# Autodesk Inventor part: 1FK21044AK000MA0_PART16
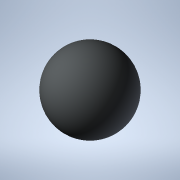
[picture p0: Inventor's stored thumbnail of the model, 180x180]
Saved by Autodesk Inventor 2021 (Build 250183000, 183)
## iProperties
Created: 2025-04
Part Number: 1FK21044AK000MA0_PART16
Material: Generic
Catalog Web Link: www.3dfindit.com
Description: -Servo synchronous motor
Document SubType Name: Modeling
Designer: psAdmin
Mass: 0.137258 g
Surface Area: 1.2868 cm^2
Volume: 0.137258 cm^3
Density: 1 g/cm^3
Appearance: PSOLRGB-212-217-219
Category: PARTsolutions
Title: 1FK21044AK000MA0_PART16
Author: Cadenas PARTsolutions
Comments: Servo synchronous motor
Sending System: PARTsolutions
Preprocessor: ST-DEVELOPER v19.3
PSOL_IDENT_0: {$CADENAS_DATA/23d-libs/siemens_ag/_cat_/87/f4/1fk21044ak000ma0.prj},216 {VTYP=3D},{NB=1FK21044AK000
PSOL_IDENT_1: MA0_PART16},{LINA=1FK21044AK000MA0_PART16},{NN=1FK21044AK000MA0_PART16},{NOPRJ=TRUE},{DATE=19.08.202
PSOL_IDENT_2: 5 14:00:48},{GEOMDATE=30.07.2025 02:00:50},{VERSION=},{LINEID=10},{WBVAR=},{WBNUMERIC=}  {NB=1FK2104
PSOL_IDENT_3: 4AK000MA0_PART16},{LINA=1FK21044AK000MA0_PART16},{KT=DUMMY},{PREVIEW=../../../_pool_/cb/72/p_d211_xx
PSOL_IDENT_4: _00434j.png},{DESCSHORT=SIMOTICS S-1FK2 HD, SINAMICS S210 3AC 400V-480V, 0.95 Nm, 6000 rpm},{DESCLON
PSOL_IDENT_5: G=SIMOTICS S-1FK2 HD servo motor M0=1.27 Nm; PN = 0.6 kW at nN=6000 rpm (380-480 V); PN = 0.4 kW at
PSOL_IDENT_6: nN=3000 rpm (200-240 V); degree of protection IP64; cylindrical shaft D19x40mm; absolute encoder 22-
PSOL_IDENT_7: bit + 12-bit multiturn (encoder AM22DQC); with OCC interface; plug size M17, rotatable; SIMOTICS S-1
PSOL_IDENT_8: FK2 servomotorfor a wide range of uses in industrial environments. SIMOTICS S‑1FK2 servomotors are c
PSOL_IDENT_9: ompact synchronous motors with a high dynamic performance that set themselves apart as a result of t
PSOL_IDENT_10: heir high power density, degree of protection and overload capability. The motors are available in t
PSOL_IDENT_11: wo variants: as High Dynamic variant (highest dynamic performance as a result of the low intrinsic m
PSOL_IDENT_12: oment of inertia for applications demanding a high dynamic performance with low moved masses) - and
PSOL_IDENT_13: as Compact variant (precise and stable closed-loop control for medium up to large moved masses as a
PSOL_IDENT_14: result of a medium intrinsic moment of inertia). SIMOTICSS‑1FK2 servomotors fully exploit their stre
PSOL_IDENT_15: ngths in a system with the SINAMICSS210 frequency converter and simple connection using the one cabl
PSOL_IDENT_16: e connection (OCC). Advantages include the short control and positioning times, fast and precise cor
PSOL_IDENT_17: rection of disturbing quantities as well as stable control with a high dynamic performance. The serv
PSOL_IDENT_18: o motors can be configured to address a wide range of requirements. For example with and without hol
PSOL_IDENT_19: ding brake, IP64 or IP65 degree of protection, singleturn or multiturn absolute encoders - to name j
PSOL_IDENT_20: ust a few. Further, the servomotors are available in different shaft heights extending from 20 to 10
PSOL_IDENT_21: 0. A shaft sealing ring is available to achieve an IP65 degree of protection and for subsequent moun
PSOL_IDENT_22: ting at the motor or as spare part. SIMOTICS - the optimum motor for each and every motion control a
PSOL_IDENT_23: pplication.},{INTNO=195125056312},{SUPPLIERALTNO=1FK2104-4AK00-0MA0},{MANUID=1FK21044AK000MA0},{MANU
PSOL_IDENT_24: NAME=Siemens},{MANUTYPEDESC=Synchronous motor 1FK2-HD 1,27 Nm},{AAU732=SIMOTICS},{AAO057=S-1FK2},{AA
PSOL_IDENT_25: U734=SIMOTICS S-1FK2 HD servo motor M0=1.27 Nm; PN = 0.6 kW at nN=6000 rpm (380-480 V); PN = 0.4 kW
PSOL_IDENT_26: at nN=3000 rpm (200-240 V); degree of protection IP64; cylindrical shaft D19x40mm; absolute encoder
PSOL_IDENT_27: 22-bit + 12-bit multiturn (encoder AM22DQC); with OCC interface; plug size M17, rotatable;},{AAW338=
PSOL_IDENT_28: Synchronous motor 1FK2-HD 1,27 Nm},{AAO742=SIMOTICS},{AAO663=4042948690994},{NOCUPEROU=1},{PRICEQUAN
PSOL_IDENT_29: TITY=1},{QUANTITYMIN=1},{QUANTITYINT=1},{CTN=85015100},{COO=DE},{AAO676=1FK2104-4AK00-0MA0},{AAO677=
PSOL_IDENT_30: Siemens AG},{ORDERUNIT=C62},{CONTENTUNIT=C62}
NB: 1FK21044AK000MA0_PART16
NT: Servo synchronous motor
NBSYN: $MANUID._PART16
LINA: 1FK21044AK000MA0_PART16
CATALOG: SIEMENS
PREVIEW: ../../../_pool_/cb/72/p_d211_xx_00434j.png
DESCSHORT: SIMOTICS S-1FK2 HD, SINAMICS S210 3AC 400V-480V, 0.95 Nm, 6000 rpm
DESCLONG: SIMOTICS S-1FK2 HD servo motor M0=1.27 Nm; PN = 0.6 kW at nN=6000 rpm (380-480 V); PN = 0.4 kW at nN=3000 rpm (200-240 V); degree of protection IP64; cylindrica
INTNO: 195125056312
SUPPLIERALTNO: 1FK2104-4AK00-0MA0
MANUID: 1FK21044AK000MA0
MANUNAME: Siemens
MANUTYPEDESC: Synchronous motor 1FK2-HD 1,27 Nm
AAU732: SIMOTICS
AAO057: S-1FK2
AAU734: SIMOTICS S-1FK2 HD servo motor M0=1.27 Nm; PN = 0.6 kW at nN=6000 rpm (380-480 V); PN = 0.4 kW at nN=3000 rpm (200-240 V); degree of protection IP64; cylindrica
AAW338: Synchronous motor 1FK2-HD 1,27 Nm
AAO742: SIMOTICS
AAO663: 4042948690994.0
NOCUPEROU: 1
PRICEQUANTITY: 1
QUANTITYMIN: 1
QUANTITYINT: 1
CTN: 85015100
COO: DE
ARTICLENO: 1FK21044AK000MA0_PART16
BOMINFO: 1FK21044AK000MA0_PART16
CREATOR: CADENAS GmbH
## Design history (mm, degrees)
feature "2025_04_17_15_37_40_0588"
body "Solid1"
